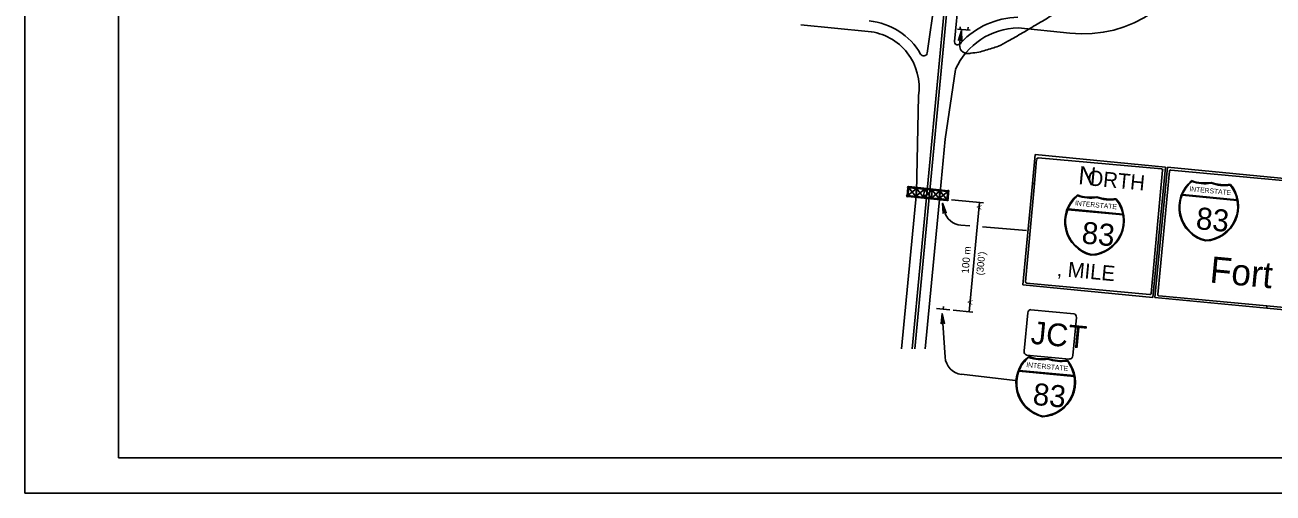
# Model space of a CAD drawing. Extents: x 640994 to 644422, y 298458 to 299646.
# Drawn here: x 640994 to 641528, y 298458 to 298658 of the extents above; entities that cross this region are included whole.
import ezdxf

# ---------------------------------------------------------------- set-up
doc = ezdxf.new("R2010")
doc.units = 0
for name, color, linetype in [('1', 7, 'Continuous'), ('2', 7, 'Continuous'), ('XCS-GRID-MIN', 7, 'Continuous')]:
    doc.layers.add(name, color=color, linetype=linetype)

msp = doc.modelspace()

# ---------------------------------------------------------------- linework, layer by layer
at = {"layer": '1'}
for p, q in [((641034.31, 299036.63), (641034.31, 298472.63)), ((641820.31, 298472.63), (641034.31, 298472.63)), ((641034.31, 298472.63), (641620.31, 298472.63))]:
    msp.add_line(p, q, dxfattribs=at)
at = {"layer": '2'}
for p, q in [((641418.56, 298990.13), (641373.69, 298519.25)), ((641419.69, 298990.13), (641374.81, 298519.25)), ((641394.19, 298675.5), (641391.81, 298650.75)), ((641380.19, 298645.63), (641383.44, 298668.63)), ((641354.94, 298655), (641326.06, 298657.75)), ((641398.56, 298655.5), (641393.06, 298656)), ((641394.19, 298655.88), (641394.19, 298657)), ((641397.56, 298655.63), (641397.69, 298656.75)), ((641419.06, 298656.5), (641441.16, 298654.21)), ((641387.81, 298608.88), (641392.31, 298638.75)), ((641375.56, 298586.13), (641376.44, 298627.5)), ((641385.69, 298586.13), (641387.81, 298608.88)), ((641425.15, 298590), (641426.31, 298602.38)), ((641426.94, 298600.25), (641426, 298589.91)), ((641426.31, 298602.38), (641482.06, 298597.01)), ((641480.31, 298596.25), (641427.56, 298600.88)), ((641475.94, 298542.88), (641480.81, 298595.63)), ((641482.06, 298597), (641476.69, 298541.25)), ((641477.57, 298541.17), (641482.95, 298596.92)), ((641483.82, 298595.29), (641478.82, 298542.54)), ((641482.95, 298596.91), (641572.07, 298588.42)), ((641421.06, 298546.63), (641425.15, 298590)), ((641426, 298589.91), (641422.19, 298547.88)), ((641425.15, 298590), (641426, 298589.91)), ((641426, 298589.91), (641425.15, 298590)), ((641493.32, 298590.79), (641493.32, 298590.79)), ((641501.57, 298590.04), (641501.57, 298590.04)), ((641509.7, 298589.29), (641509.7, 298589.29)), ((641375.56, 298586.13), (641369.19, 298519.25)), ((641371.81, 298588.13), (641371.56, 298584.88)), ((641371.81, 298584.38), (641388.56, 298582.75)), ((641372.31, 298588.13), (641371.94, 298584.88)), ((641371.94, 298584.88), (641375.56, 298587.88)), ((641389.06, 298586.88), (641372.31, 298588.63)), ((641372.31, 298588.13), (641375.31, 298584.38)), ((641375.31, 298584.38), (641378.94, 298587.5)), ((641375.56, 298587.88), (641378.56, 298584.13)), ((641378.56, 298584.13), (641382.31, 298587.13)), ((641378.94, 298587.5), (641381.94, 298583.75)), ((641385.69, 298586.13), (641379.31, 298519.25)), ((641380.44, 298585.63), (641380.44, 298585.63)), ((641380.44, 298585.63), (641380.44, 298585.63)), ((641381.94, 298583.75), (641385.56, 298586.88)), ((641382.31, 298587.13), (641385.31, 298583.5)), ((641385.31, 298583.5), (641388.94, 298586.5)), ((641385.56, 298586.88), (641388.56, 298583.13)), ((641385.56, 298586.13), (641385.56, 298586.13)), ((641388.56, 298583.13), (641388.94, 298586.5)), ((641389.06, 298583.13), (641389.31, 298586.5)), ((641444.44, 298584.75), (641444.44, 298584.75)), ((641452.69, 298583.88), (641452.69, 298583.88)), ((641489.2, 298584.92), (641512.7, 298582.67)), ((641512.7, 298583.04), (641489.32, 298585.29)), ((641386.69, 298581.5), (641387.56, 298578.25)), ((641390.56, 298583), (641404.19, 298581.75)), ((641398.06, 298535.13), (641402.56, 298581.88)), ((641440.31, 298578.75), (641463.94, 298576.63)), ((641463.81, 298576.88), (641440.44, 298579.13)), ((641460.94, 298583.13), (641460.94, 298583.13)), ((641394.56, 298572.13), (641398.44, 298571.88)), ((641403.81, 298571.38), (641422.56, 298569.88)), ((641476.69, 298541.25), (641421.06, 298546.63)), ((641422.69, 298547.38), (641475.31, 298542.5)), ((641525.37, 298536.61), (641477.57, 298541.17)), ((641479.2, 298541.92), (641525.47, 298537.63)), ((641389.81, 298536), (641384.19, 298536.5)), ((641386.94, 298536.25), (641387.06, 298537.38)), ((641391.31, 298535.75), (641399.69, 298535)), ((641424.44, 298536), (641442.94, 298534.25)), ((641525.37, 298536.61), (641525.47, 298537.63)), ((641525.47, 298537.63), (641525.37, 298536.61)), ((641566.82, 298532.67), (641525.37, 298536.61)), ((641525.47, 298537.63), (641565.45, 298533.92)), ((641386.56, 298534.38), (641387.81, 298515.75)), ((641421.69, 298518.38), (641423.19, 298534.63)), ((641443.94, 298532.63), (641442.44, 298516.38)), ((641441.06, 298514.88), (641422.69, 298516.63)), ((641423.56, 298515.63), (641423.56, 298515.63)), ((641431.69, 298514.88), (641431.69, 298514.88)), ((641419.31, 298509.75), (641442.94, 298507.5)), ((641442.94, 298507.88), (641419.56, 298510)), ((641439.94, 298514.13), (641439.94, 298514.13)), ((641394.81, 298508.38), (641417.81, 298505.75))]:
    msp.add_line(p, q, dxfattribs=at)
for points in [[(641393.69, 298651.35), (641393.97, 298651.4), (641394.85, 298655.37), (641393.69, 298651.35), (641393.49, 298651.21), (641394.85, 298655.37), (641394.49, 298651.3), (641394.74, 298651.17), (641394.85, 298655.37), (641394.95, 298650.86), (641394.74, 298651.17)], [(641570.89, 298587.75), (641484.32, 298595.67)], [(641387.06, 298577.5), (641387.31, 298577.63), (641386.69, 298581.5), (641387.06, 298577.5), (641386.94, 298577.25), (641386.69, 298581.5), (641387.81, 298577.75), (641388.06, 298577.63), (641386.69, 298581.5), (641388.31, 298577.5), (641388.06, 298577.63)], [(641386.44, 298530.25), (641386.69, 298530.5), (641386.56, 298534.38), (641386.44, 298530.25), (641386.19, 298530), (641386.56, 298534.38), (641387.06, 298530.5), (641387.31, 298530.38), (641386.56, 298534.38), (641387.56, 298530.13), (641387.31, 298530.38)]]:
    msp.add_lwpolyline(points, dxfattribs=at)
for points in [[(641375.31, 298584.38), (641371.94, 298584.88), (641372.31, 298588.13), (641375.56, 298587.88)], [(641378.56, 298584.13), (641375.31, 298584.38), (641375.56, 298587.88), (641378.94, 298587.5)], [(641381.94, 298583.75), (641378.56, 298584.13), (641378.94, 298587.5), (641382.31, 298587.13)], [(641385.31, 298583.5), (641381.94, 298583.75), (641382.31, 298587.13), (641385.56, 298586.88)], [(641388.56, 298583.13), (641385.31, 298583.5), (641385.56, 298586.88), (641388.94, 298586.5)]]:
    msp.add_lwpolyline(points, close=True, dxfattribs=at)
for centre in [(641371.67, 298584.6), (641372.03, 298588.37), (641389.17, 298586.74), (641388.81, 298582.97)]:
    msp.add_circle(centre, 0.3, dxfattribs=at)
for centre, radius, start, end in [((641446.85, 298706.2), 52.3, 263.7511, 345.8438), ((641352.67, 298631.09), 28.5, 29.9854, 84.5024), ((641419.72, 298626.46), 34.57, 91.3421, 136.5451), ((641352.67, 298631.09), 24.02, 351.1999, 84.5024), ((641419.72, 298626.45), 30.1, 91.3442, 155.7409), ((641393.23, 298650.69), 1.47, 163.8304, 341.9987), ((641378.71, 298646.06), 1.53, 208.2475, 339.8234), ((641427.59, 298600.33), 0.528, 84.9959, 174.9819), ((641480.37, 298595.7), 0.528, 354.5597, 84.8056), ((641484.26, 298595.22), 0.528, 84.2894, 175.6013), ((641502.65, 298579.79), 14.78, 129.5662, 256.4361), ((641502.65, 298579.79), 14.47, 130.2586, 157.7735), ((641498.95, 298607.18), 16.98, 250.3162, 278.8163), ((641498.95, 298607.18), 17.29, 250.9067, 278.5552), ((641498.49, 298580.19), 14.78, 272.6963, 39.5662), ((641507.28, 298606.39), 17.29, 250.5773, 278.2257), ((641507.28, 298606.39), 16.98, 250.3162, 278.8163), ((641498.49, 298580.19), 14.47, 11.359, 38.8739), ((641453.8, 298573.67), 14.78, 129.5662, 256.4361), ((641453.8, 298573.67), 14.47, 130.2586, 157.7735), ((641450.11, 298601.05), 16.98, 250.3162, 278.8163), ((641450.11, 298601.05), 17.29, 250.9067, 278.5552), ((641458.43, 298600.26), 17.29, 250.5773, 278.2257), ((641458.43, 298600.26), 16.98, 250.3162, 278.8163), ((641502.65, 298579.79), 14.47, 159.0531, 256.4361), ((641395.3, 298580.09), 8, 192.9946, 265.0303), ((641453.8, 298573.67), 14.47, 159.0531, 256.4361), ((641449.64, 298574.06), 14.78, 272.6963, 39.5662), ((641449.64, 298574.06), 14.47, 11.359, 38.8739), ((641498.49, 298580.19), 14.47, 272.6964, 10.0794), ((641449.64, 298574.06), 14.47, 272.6964, 10.0794), ((641422.75, 298547.92), 0.528, 174.5597, 264.2894), ((641475.39, 298542.97), 0.528, 262.875, 354.8056), ((641479.27, 298542.48), 0.528, 174.0939, 265.2364), ((641395.77, 298516.32), 8, 184.4846, 263.4181), ((641432.89, 298504.59), 14.78, 129.5662, 256.4361), ((641432.89, 298504.59), 14.47, 130.2586, 157.7735), ((641429.2, 298531.97), 16.98, 250.3162, 278.8163), ((641429.2, 298531.97), 17.29, 250.9067, 278.5552), ((641428.73, 298504.98), 14.78, 272.6963, 39.5662), ((641437.52, 298531.18), 17.29, 250.5773, 278.2257), ((641437.52, 298531.18), 16.98, 250.3162, 278.8163), ((641432.89, 298504.59), 14.47, 159.0531, 256.4361), ((641428.73, 298504.98), 14.47, 11.359, 38.8739), ((641428.73, 298504.98), 14.47, 272.6964, 10.0794)]:
    msp.add_arc(centre, radius, start, end, dxfattribs=at)
for centre, major_axis, start_param, end_param in [((641424.34, 298534.49), (-0.15, -1.55), 3.141593, 4.712389), ((641442.77, 298532.73), (0.15, 1.55), 4.712389, 6.283185), ((641422.79, 298518.25), (-0.15, -1.55), 4.712389, 6.283185), ((641441.23, 298516.5), (0.15, 1.55), 3.141593, 4.712389)]:
    msp.add_ellipse(centre, major_axis=major_axis, ratio=0.769266, start_param=start_param, end_param=end_param, dxfattribs=at)
msp.add_spline([(641394.56, 298653.56), (641394.35, 298651.89), (641394.44, 298647.29), (641396.89, 298645.56), (641398.8, 298645.69), (641402.25, 298646.14), (641405.09, 298646.96), (641410.63, 298648.71), (641414.66, 298650.8), (641420.94, 298654.38), (641427.19, 298658.13), (641433.06, 298661.63), (641438.81, 298665.63)], degree=3, dxfattribs=at)
at = {"layer": 'XCS-GRID-MIN'}
msp.add_lwpolyline([(640994.31, 299051.63), (641835.31, 299051.63), (641835.31, 298457.63), (640994.31, 298457.63)], close=True, dxfattribs=at)

# ---------------------------------------------------------------- texts
at = {"layer": '2'}
for s, height, rotation, p in [('N', 7.75, 354.5817, (641444.56, 298589.75)), ('ORTH', 6.5, 354.5683, (641448.44, 298589.25)), ('INTERSTATE', 2.089, 354.5668, (641492.2, 298586.67)), ('A', 2.09, 84.5681, (641403.31, 298578.75)), ('INTERSTATE', 2.089, 354.5668, (641443.31, 298580.63)), ('83', 9.406, 354.5658, (641494.82, 298570.54)), ('83', 9.406, 354.5658, (641445.94, 298564.38)), ('100 m', 3.134, 84.5681, (641397.85, 298551.35)), ("(300')", 3, 84.5019, (641404.07, 298550.61)), ('Fort', 11.25, 354.5683, (641500.7, 298547.67)), ('‚ MILE', 6.493, 354.5683, (641435.69, 298550.5)), ('A', 2.09, 84.5681, (641399.44, 298538.13)), ('JCT', 9.706, 354.5666, (641424.19, 298521.5)), ('INTERSTATE', 2.089, 354.5668, (641422.44, 298511.5)), ('83', 9.406, 354.5658, (641425.06, 298495.38))]:
    msp.add_text(s, height=height, rotation=rotation, dxfattribs=at).set_placement(p)

doc.saveas('drawing.dxf')
